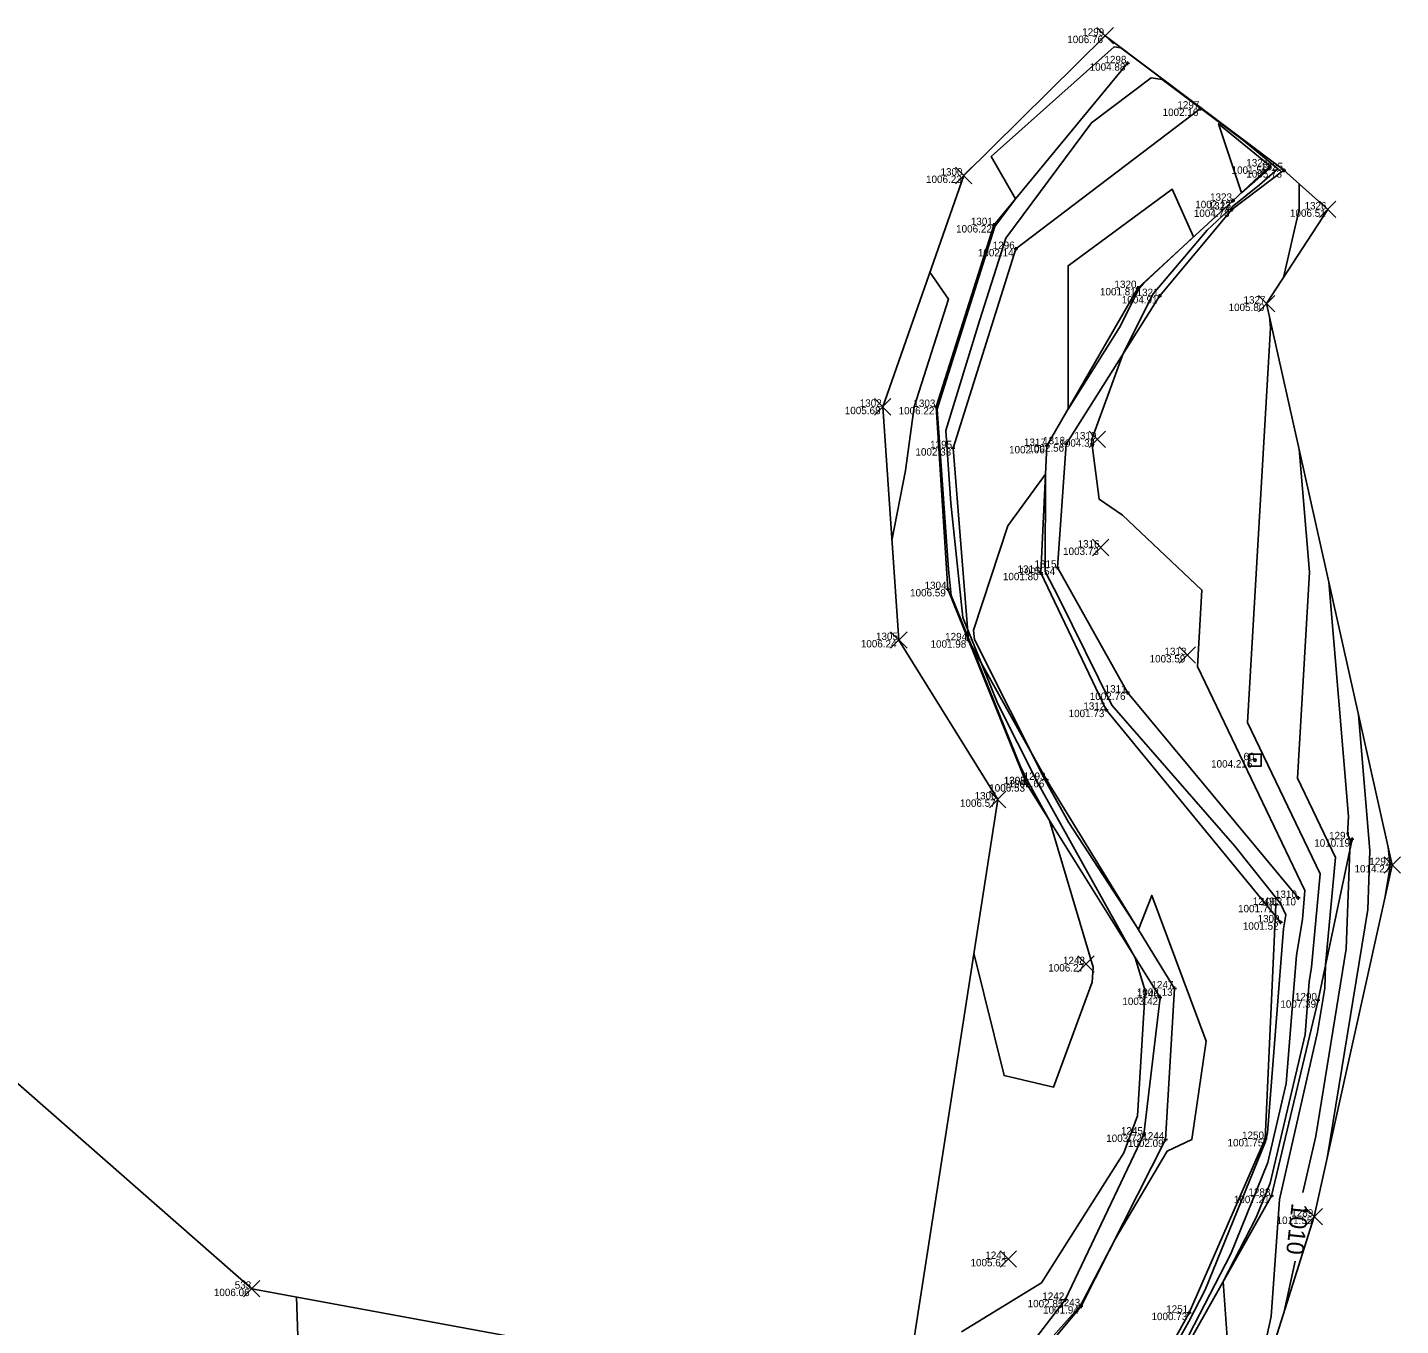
# Model space of a CAD drawing. Extents: x 2354693 to 2355622, y 637071 to 710080.
# Drawn here: x 2355399.4 to 2355622.2, y 709573.6 to 709784.2 of the extents above; entities that cross this region are included whole.
import ezdxf

# ---------------------------------------------------------------- set-up
doc = ezdxf.new("R2010")
doc.units = 0
for name, color, linetype in [('Default', 7, 'Continuous'), ('DT_X_Contour_Major', 7, 'Continuous'), ('DT_X_Contour_Minor', 7, 'Continuous'), ('HY_X_Water_Edge', 7, 'Continuous'), ('SV_X_Control_Cells_Found', 7, 'Continuous'), ('SV_X_Random_Point', 7, 'Continuous'), ('SV_X_Shot_Marker', 7, 'Continuous'), ('SV_X_Text_Elevation', 7, 'Continuous'), ('SV_X_Text_Name', 7, 'Continuous'), ('SV_X_Toe_of_Slope', 7, 'Continuous'), ('SV_X_Top_of_Bank', 7, 'Continuous')]:
    doc.layers.add(name, color=color, linetype=linetype)

msp = doc.modelspace()

# ---------------------------------------------------------------- linework, layer by layer
at = {"layer": 'Default'}
for points in [[(2355589.64, 709532.44), (2355608.23, 709591.27), (2355620.9, 709648.31), (2355600.49, 709739.39), (2355610.41, 709754.67), (2355603.31, 709761.03), (2355574.3, 709782.85), (2355551.34, 709760.16), (2355538.2, 709722.65), (2355540.82, 709684.81), (2355556.87, 709658.95), (2355543.09, 709570.18)], [(2355589.64, 709532.44), (2355608.23, 709591.27), (2355620.9, 709648.31), (2355600.49, 709739.39), (2355610.41, 709754.67), (2355603.31, 709761.03), (2355574.3, 709782.85), (2355551.34, 709760.16), (2355538.2, 709722.65), (2355540.82, 709684.81), (2355556.87, 709658.95), (2355543.09, 709570.18)], [(2355527.94, 709562.59), (2355435.81, 709579.57), (2355393.46, 709616.64), (2355345.61, 709656.34), (2355300.99, 709689.27), (2355286.64, 709699.9), (2355266.95, 709650.86), (2355232.94, 709607.57), (2355192.85, 709575.71), (2355160.05, 709542.81)], [(2355527.94, 709562.59), (2355435.81, 709579.57), (2355393.46, 709616.64), (2355345.61, 709656.34), (2355300.99, 709689.27), (2355286.64, 709699.9), (2355266.95, 709650.86), (2355232.94, 709607.57), (2355192.85, 709575.71), (2355160.05, 709542.81)]]:
    msp.add_lwpolyline(points, dxfattribs=at)
at = {"layer": 'DT_X_Contour_Major'}
for points in [[(2355610.61, 709694.24), (2355613.77, 709656.2), (2355613.6, 709653.34), (2355614.13, 709652.24), (2355613.99, 709650.75), (2355613.43, 709634.7), (2355608.47, 709604.33), (2355606.37, 709595.16)], [(2355610.61, 709694.24), (2355613.77, 709656.2), (2355613.6, 709653.34), (2355614.13, 709652.24), (2355613.99, 709650.75), (2355613.43, 709634.7), (2355608.47, 709604.33), (2355606.37, 709595.16)], [(2355605.14, 709584.05), (2355603.36, 709575.86)], [(2355605.14, 709584.05), (2355603.36, 709575.86)]]:
    msp.add_lwpolyline(points, dxfattribs=at)
at = {"layer": 'DT_X_Contour_Minor'}
for points in [[(2355553, 709634.03), (2355557.89, 709614.16), (2355565.94, 709612.27), (2355572.21, 709629.3), (2355572.35, 709631.71), (2355565.27, 709655.55), (2355561.95, 709661.5), (2355560.63, 709664.14), (2355560.61, 709664.14), (2355549.33, 709692.03), (2355548.89, 709696.25), (2355547.05, 709722.24), (2355547.6, 709724.01), (2355556.42, 709751.92), (2355559.77, 709756.4), (2355555.82, 709763.23), (2355575.76, 709781.05), (2355576.84, 709780.91), (2355595.66, 709766.78)], [(2355553, 709634.03), (2355557.89, 709614.16), (2355565.94, 709612.27), (2355572.21, 709629.3), (2355572.35, 709631.71), (2355565.27, 709655.55), (2355561.95, 709661.5), (2355560.63, 709664.14), (2355560.61, 709664.14), (2355549.33, 709692.03), (2355548.89, 709696.25), (2355547.05, 709722.24), (2355547.6, 709724.01), (2355556.42, 709751.92), (2355559.77, 709756.4), (2355555.82, 709763.23), (2355575.76, 709781.05), (2355576.84, 709780.91), (2355595.66, 709766.78)], [(2355550.99, 709572.6), (2355563.99, 709580.52), (2355577.32, 709601.59), (2355579.55, 709607.64), (2355580.78, 709627.91), (2355579.19, 709633.25), (2355563.25, 709661.79), (2355556.89, 709674.47), (2355556.88, 709674.47), (2355551.22, 709688.48), (2355549.28, 709706.99), (2355548.45, 709718.8), (2355553.93, 709736.58), (2355558.18, 709750.02), (2355572.11, 709768.7), (2355581.75, 709776.01), (2355583.57, 709775.77), (2355596.76, 709765.86), (2355602.34, 709761.28), (2355599.33, 709758.64), (2355594.9, 709755.07), (2355590.83, 709751.31), (2355582.08, 709741), (2355577.24, 709731.27), (2355572.08, 709717.21), (2355573.34, 709707.66), (2355577.14, 709705.05), (2355590.01, 709692.92), (2355589.29, 709680.51), (2355606.72, 709644.18), (2355606.3, 709639.49), (2355605.34, 709633.67), (2355603.7, 709612.85), (2355600.7, 709600.07), (2355594.68, 709585.25), (2355587.86, 709572.01)], [(2355550.99, 709572.6), (2355563.99, 709580.52), (2355577.32, 709601.59), (2355579.55, 709607.64), (2355580.78, 709627.91), (2355579.19, 709633.25), (2355563.25, 709661.79), (2355556.89, 709674.47), (2355556.88, 709674.47), (2355551.22, 709688.48), (2355549.28, 709706.99), (2355548.45, 709718.8), (2355553.93, 709736.58), (2355558.18, 709750.02), (2355572.11, 709768.7), (2355581.75, 709776.01), (2355583.57, 709775.77), (2355596.76, 709765.86), (2355602.34, 709761.28), (2355599.33, 709758.64), (2355594.9, 709755.07), (2355590.83, 709751.31), (2355582.08, 709741), (2355577.24, 709731.27), (2355572.08, 709717.21), (2355573.34, 709707.66), (2355577.14, 709705.05), (2355590.01, 709692.92), (2355589.29, 709680.51), (2355606.72, 709644.18), (2355606.3, 709639.49), (2355605.34, 709633.67), (2355603.7, 709612.85), (2355600.7, 709600.07), (2355594.68, 709585.25), (2355587.86, 709572.01)], [(2355596.42, 709757.37), (2355592.7, 709768.57), (2355601.22, 709761.58), (2355596.42, 709757.37)], [(2355596.42, 709757.37), (2355592.7, 709768.57), (2355601.22, 709761.58), (2355596.42, 709757.37)], [(2355568.3, 709722.28), (2355568.28, 709745.54), (2355585.19, 709757.94), (2355588.66, 709750.24), (2355580.55, 709742.73), (2355579.8, 709741.84), (2355576.65, 709735.52), (2355568.3, 709722.28)], [(2355568.3, 709722.28), (2355568.28, 709745.54), (2355585.19, 709757.94), (2355588.66, 709750.24), (2355580.55, 709742.73), (2355579.8, 709741.84), (2355576.65, 709735.52), (2355568.3, 709722.28)], [(2355605.76, 709758.83), (2355605.79, 709754.67), (2355603.24, 709743.63)], [(2355605.76, 709758.83), (2355605.79, 709754.67), (2355603.24, 709743.63)], [(2355539.7, 709700.97), (2355541.89, 709712.32), (2355543.32, 709722.63), (2355548.87, 709740.1), (2355545.86, 709744.51)], [(2355539.7, 709700.97), (2355541.89, 709712.32), (2355543.32, 709722.63), (2355548.87, 709740.1), (2355545.86, 709744.51)], [(2355600.97, 709737.27), (2355601.12, 709735.48), (2355597.4, 709671.45), (2355609.19, 709646.86), (2355607.81, 709631.74), (2355607.42, 709629.35), (2355606.75, 709620.83), (2355601.07, 709596.69), (2355598.81, 709591.11), (2355593.45, 709580.72), (2355594.25, 709569.36), (2355593.09, 709546.68), (2355590.78, 709536.05)], [(2355600.97, 709737.27), (2355601.12, 709735.48), (2355597.4, 709671.45), (2355609.19, 709646.86), (2355607.81, 709631.74), (2355607.42, 709629.35), (2355606.75, 709620.83), (2355601.07, 709596.69), (2355598.81, 709591.11), (2355593.45, 709580.72), (2355594.25, 709569.36), (2355593.09, 709546.68), (2355590.78, 709536.05)], [(2355605.79, 709715.76), (2355607.44, 709695.84), (2355605.5, 709662.4), (2355611.66, 709649.55), (2355610.07, 709632.1), (2355609.94, 709628.32), (2355608.77, 709621.18), (2355602.57, 709594.04), (2355601.22, 709575.06), (2355597.07, 709555.96)], [(2355605.79, 709715.76), (2355607.44, 709695.84), (2355605.5, 709662.4), (2355611.66, 709649.55), (2355610.07, 709632.1), (2355609.94, 709628.32), (2355608.77, 709621.18), (2355602.57, 709594.04), (2355601.22, 709575.06), (2355597.07, 709555.96)], [(2355556.66, 709561.53), (2355570.22, 709576.8), (2355570.74, 709577.68), (2355575.9, 709587.59), (2355584.36, 709601.9), (2355588.38, 709603.79), (2355590.7, 709619.75), (2355581.86, 709643.38), (2355579.69, 709637.83), (2355568.36, 709655.25), (2355564.55, 709662.08), (2355553.16, 709684.8), (2355553.16, 709684.8), (2355553.11, 709684.92), (2355552.96, 709686.4), (2355558.49, 709703.33), (2355564.64, 709711.73), (2355564.59, 709695.94), (2355566.8, 709691.65), (2355575.39, 709674.22), (2355595.34, 709651.37), (2355602.74, 709642.08), (2355603.62, 709640.2), (2355603.26, 709637.98), (2355600.65, 709604.87), (2355600.32, 709603.44), (2355590.55, 709579.39), (2355587.9, 709574.25), (2355577.82, 709556.22)], [(2355556.66, 709561.53), (2355570.22, 709576.8), (2355570.74, 709577.68), (2355575.9, 709587.59), (2355584.36, 709601.9), (2355588.38, 709603.79), (2355590.7, 709619.75), (2355581.86, 709643.38), (2355579.69, 709637.83), (2355568.36, 709655.25), (2355564.55, 709662.08), (2355553.16, 709684.8), (2355553.16, 709684.8), (2355553.11, 709684.92), (2355552.96, 709686.4), (2355558.49, 709703.33), (2355564.64, 709711.73), (2355564.59, 709695.94), (2355566.8, 709691.65), (2355575.39, 709674.22), (2355595.34, 709651.37), (2355602.74, 709642.08), (2355603.62, 709640.2), (2355603.26, 709637.98), (2355600.65, 709604.87), (2355600.32, 709603.44), (2355590.55, 709579.39), (2355587.9, 709574.25), (2355577.82, 709556.22)], [(2355615.43, 709672.73), (2355617.26, 709650.63), (2355616.93, 709641.07), (2355610.33, 709600.73)], [(2355615.43, 709672.73), (2355617.26, 709650.63), (2355616.93, 709641.07), (2355610.33, 709600.73)], [(2355620.25, 709651.22), (2355620.47, 709648.58), (2355620.43, 709647.44), (2355619.64, 709642.63)], [(2355620.25, 709651.22), (2355620.47, 709648.58), (2355620.43, 709647.44), (2355619.64, 709642.63)], [(2355443.41, 709568.67), (2355443.07, 709578.23)], [(2355443.41, 709568.67), (2355443.07, 709578.23)]]:
    msp.add_lwpolyline(points, dxfattribs=at)
at = {"layer": 'HY_X_Water_Edge'}
for points in [[(2355444.84, 709409.8), (2355493.39, 709446.46), (2355518.03, 709448.34), (2355539.67, 709472.16), (2355542.83, 709490.32), (2355537.69, 709525.78), (2355546.35, 709545.98), (2355551.46, 709553.96), (2355570.39, 709576.73), (2355584.11, 709603.77), (2355585.55, 709628.29), (2355564.78, 709662.12), (2355552.11, 709684.77), (2355549.62, 709715.93), (2355559.81, 709748.25), (2355589.77, 709771.03)], [(2355601.98, 709641.84), (2355600.27, 709603.87), (2355587.93, 709575.67), (2355574.93, 709552.02), (2355564.16, 709527.42), (2355560.86, 709513.6), (2355569.23, 709466.41), (2355552.57, 709436.48), (2355543.58, 709440.01), (2355530.89, 709431.5), (2355507.81, 709418.76), (2355493.48, 709407.24), (2355475.84, 709401.85), (2355468.12, 709405.11), (2355452.68, 709393.73)]]:
    msp.add_lwpolyline(points, dxfattribs=at)
at = {"layer": 'SV_X_Control_Cells_Found'}
msp.add_lwpolyline([(2355597.61, 709666.31), (2355599.59, 709666.31), (2355599.59, 709664.33), (2355597.61, 709664.33), (2355597.61, 709666.31)], dxfattribs=at)
msp.add_circle((2355598.6, 709665.32), 0.2, dxfattribs=at)
at = {"layer": 'SV_X_Random_Point'}
for p, q in [((2355572.97, 709781.52), (2355575.64, 709784.19)), ((2355572.97, 709784.19), (2355575.64, 709781.52)), ((2355550.01, 709758.83), (2355552.68, 709761.5)), ((2355550.01, 709761.5), (2355552.68, 709758.83)), ((2355609.07, 709753.34), (2355611.74, 709756.01)), ((2355609.07, 709756.01), (2355611.74, 709753.34)), ((2355599.16, 709738.06), (2355601.82, 709740.73)), ((2355599.16, 709740.73), (2355601.82, 709738.06)), ((2355536.86, 709721.31), (2355539.53, 709723.98)), ((2355536.86, 709723.98), (2355539.53, 709721.31)), ((2355571.71, 709716.03), (2355574.38, 709718.7)), ((2355571.71, 709718.7), (2355574.38, 709716.03)), ((2355572.25, 709698.48), (2355574.92, 709701.15)), ((2355572.25, 709701.15), (2355574.92, 709698.48)), ((2355539.48, 709683.47), (2355542.15, 709686.14)), ((2355539.48, 709686.14), (2355542.15, 709683.47)), ((2355586.3, 709681.03), (2355588.97, 709683.7)), ((2355586.3, 709683.7), (2355588.97, 709681.03)), ((2355555.54, 709657.61), (2355558.2, 709660.28)), ((2355555.54, 709660.28), (2355558.2, 709657.61)), ((2355619.57, 709646.97), (2355622.23, 709649.64)), ((2355619.57, 709649.64), (2355622.23, 709646.97)), ((2355569.88, 709630.9), (2355572.54, 709633.57)), ((2355569.88, 709633.57), (2355572.54, 709630.9)), ((2355606.9, 709589.94), (2355609.57, 709592.61)), ((2355606.9, 709592.61), (2355609.57, 709589.94)), ((2355557.24, 709583.06), (2355559.91, 709585.73)), ((2355557.24, 709585.73), (2355559.91, 709583.06)), ((2355434.48, 709578.23), (2355437.14, 709580.9)), ((2355434.48, 709580.9), (2355437.14, 709578.23))]:
    msp.add_line(p, q, dxfattribs=at)
at = {"layer": 'SV_X_Shot_Marker'}
for p, q in [((2355578.23, 709778.38), (2355577.63, 709778.38)), ((2355577.93, 709778.68), (2355577.93, 709778.08)), ((2355590.07, 709771.03), (2355589.47, 709771.03)), ((2355589.77, 709771.33), (2355589.77, 709770.73)), ((2355600.97, 709761.94), (2355600.97, 709761.34)), ((2355601.27, 709761.64), (2355600.67, 709761.64)), ((2355603.61, 709761.03), (2355603.01, 709761.03)), ((2355603.31, 709761.33), (2355603.31, 709760.73)), ((2355595.33, 709756.07), (2355594.73, 709756.07)), ((2355595.03, 709756.37), (2355595.03, 709755.77)), ((2355595.14, 709754.65), (2355594.54, 709754.65)), ((2355594.84, 709754.95), (2355594.84, 709754.35)), ((2355556.53, 709752.12), (2355555.93, 709752.12)), ((2355556.23, 709752.42), (2355556.23, 709751.82)), ((2355560.11, 709748.25), (2355559.51, 709748.25)), ((2355559.81, 709748.55), (2355559.81, 709747.95)), ((2355579.88, 709741.92), (2355579.28, 709741.92)), ((2355579.58, 709742.22), (2355579.58, 709741.62)), ((2355583.43, 709740.61), (2355582.83, 709740.61)), ((2355583.13, 709740.91), (2355583.13, 709740.31)), ((2355547.2, 709722.62), (2355546.6, 709722.62)), ((2355546.9, 709722.92), (2355546.9, 709722.32)), ((2355549.92, 709715.93), (2355549.32, 709715.93)), ((2355549.62, 709716.23), (2355549.62, 709715.63)), ((2355565.16, 709716.3), (2355564.56, 709716.3)), ((2355564.86, 709716.6), (2355564.86, 709716)), ((2355568.29, 709716.57), (2355567.69, 709716.57)), ((2355567.99, 709716.87), (2355567.99, 709716.27)), ((2355564.16, 709695.71), (2355563.56, 709695.71)), ((2355563.86, 709696.01), (2355563.86, 709695.41)), ((2355566.85, 709696.55), (2355566.25, 709696.55)), ((2355566.55, 709696.85), (2355566.55, 709696.25)), ((2355549.07, 709693.08), (2355548.47, 709693.08)), ((2355548.77, 709693.38), (2355548.77, 709692.78)), ((2355552.41, 709684.77), (2355551.81, 709684.77)), ((2355552.11, 709685.07), (2355552.11, 709684.47)), ((2355578.25, 709676.29), (2355577.65, 709676.29)), ((2355577.95, 709676.59), (2355577.95, 709675.99)), ((2355574.78, 709673.5), (2355574.18, 709673.5)), ((2355574.48, 709673.8), (2355574.48, 709673.2)), ((2355561.59, 709661.72), (2355561.59, 709661.12)), ((2355561.61, 709661.72), (2355561.61, 709661.12)), ((2355565.08, 709662.12), (2355564.48, 709662.12)), ((2355564.78, 709662.42), (2355564.78, 709661.82)), ((2355561.89, 709661.42), (2355561.29, 709661.42)), ((2355561.91, 709661.42), (2355561.31, 709661.42)), ((2355614.36, 709652.79), (2355614.36, 709652.19)), ((2355614.66, 709652.49), (2355614.06, 709652.49)), ((2355602.28, 709641.84), (2355601.68, 709641.84)), ((2355601.98, 709642.14), (2355601.98, 709641.54)), ((2355605.92, 709642.97), (2355605.32, 709642.97)), ((2355605.62, 709643.27), (2355605.62, 709642.67)), ((2355603.06, 709639.01), (2355602.46, 709639.01)), ((2355602.76, 709639.31), (2355602.76, 709638.71)), ((2355585.85, 709628.29), (2355585.25, 709628.29)), ((2355585.55, 709628.59), (2355585.55, 709627.99)), ((2355583.51, 709626.8), (2355582.91, 709626.8)), ((2355583.21, 709627.1), (2355583.21, 709626.5)), ((2355609.16, 709626.36), (2355608.56, 709626.36)), ((2355608.86, 709626.66), (2355608.86, 709626.06)), ((2355580.88, 709604.58), (2355580.28, 709604.58)), ((2355580.58, 709604.88), (2355580.58, 709604.28)), ((2355584.41, 709603.77), (2355583.81, 709603.77)), ((2355584.11, 709604.07), (2355584.11, 709603.47)), ((2355600.57, 709603.87), (2355599.97, 709603.87)), ((2355600.27, 709604.17), (2355600.27, 709603.57)), ((2355601.3, 709594.95), (2355601.3, 709594.35)), ((2355601.6, 709594.65), (2355601, 709594.65)), ((2355568.13, 709577.76), (2355567.53, 709577.76)), ((2355567.83, 709578.06), (2355567.83, 709577.46)), ((2355570.39, 709577.03), (2355570.39, 709576.43)), ((2355570.69, 709576.73), (2355570.09, 709576.73)), ((2355588.23, 709575.67), (2355587.63, 709575.67)), ((2355587.93, 709575.97), (2355587.93, 709575.37))]:
    msp.add_line(p, q, dxfattribs=at)
at = {"layer": 'SV_X_Toe_of_Slope'}
for points in [[(2355444.84, 709409.8), (2355493.39, 709446.46), (2355518.03, 709448.34), (2355539.67, 709472.16), (2355542.83, 709490.32), (2355537.69, 709525.78), (2355546.35, 709545.98), (2355551.46, 709553.96), (2355570.39, 709576.73), (2355584.11, 709603.77), (2355585.55, 709628.29), (2355564.78, 709662.12), (2355552.11, 709684.77), (2355549.62, 709715.93), (2355559.81, 709748.25), (2355589.77, 709771.03)], [(2355602.76, 709639.01), (2355574.48, 709673.5), (2355563.86, 709695.71), (2355564.86, 709716.3), (2355579.58, 709741.92), (2355595.03, 709756.07), (2355600.97, 709761.64)], [(2355601.98, 709641.84), (2355600.27, 709603.87), (2355587.93, 709575.67), (2355574.93, 709552.02), (2355564.16, 709527.42), (2355560.86, 709513.6), (2355569.23, 709466.41), (2355552.57, 709436.48), (2355543.58, 709440.01), (2355530.89, 709431.5), (2355507.81, 709418.76), (2355493.48, 709407.24), (2355475.84, 709401.85), (2355468.12, 709405.11), (2355452.68, 709393.73)]]:
    msp.add_lwpolyline(points, dxfattribs=at)
at = {"layer": 'SV_X_Top_of_Bank'}
for points in [[(2355577.93, 709778.38), (2355556.23, 709752.12), (2355546.9, 709722.62), (2355548.77, 709693.08), (2355561.59, 709661.42)], [(2355605.62, 709642.97), (2355577.95, 709676.29), (2355566.55, 709696.55), (2355567.99, 709716.57), (2355583.13, 709740.61), (2355594.84, 709754.65), (2355603.31, 709761.03)], [(2355543.09, 709570.18), (2355548.89, 709553.12), (2355567.83, 709577.76), (2355580.58, 709604.58), (2355583.21, 709626.8), (2355561.61, 709661.42)], [(2355539.65, 709419.5), (2355536.88, 709428.91), (2355545.13, 709427.91), (2355562.31, 709433.11), (2355572.18, 709444.95), (2355572.3, 709459.52), (2355577.24, 709476.89), (2355570.97, 709503.21), (2355563.87, 709514.15), (2355574.03, 709537.88), (2355587.83, 709570.74), (2355601.3, 709594.65), (2355608.86, 709626.36), (2355614.36, 709652.49)]]:
    msp.add_lwpolyline(points, dxfattribs=at)

# ---------------------------------------------------------------- texts
at = {"layer": 'DT_X_Contour_Major'}
msp.add_text('1010', height=2.8, rotation=263.666, dxfattribs=at).set_placement((2355604.58, 709593.54))
msp.add_text('1010', height=2.8, rotation=263.666, dxfattribs=at).set_placement((2355604.58, 709593.54))
at = {"layer": 'SV_X_Text_Elevation'}
for s, p in [('1006.76', (2355568.15, 709781.65)), ('1004.88', (2355571.78, 709777.18)), ('1002.16', (2355583.62, 709769.83)), ('1006.23', (2355545.23, 709758.96)), ('1001.56', (2355594.82, 709760.44)), ('1005.73', (2355597.2, 709759.83)), ('1002.13', (2355588.92, 709754.87)), ('1004.78', (2355588.69, 709753.45)), ('1006.51', (2355604.29, 709753.47)), ('1006.22', (2355550.11, 709750.92)), ('1002.14', (2355553.64, 709747.05)), ('1001.81', (2355573.46, 709740.72)), ('1004.91', (2355577, 709739.41)), ('1005.80', (2355594.33, 709738.19)), ('1005.68', (2355532.05, 709721.45)), ('1006.22', (2355540.78, 709721.42)), ('1004.34', (2355566.87, 709716.17)), ('1002.33', (2355543.51, 709714.73)), ('1002.06', (2355558.71, 709715.1)), ('1002.56', (2355561.84, 709715.37)), ('1003.73', (2355567.47, 709698.61)), ('1001.80', (2355557.7, 709694.51)), ('1002.54', (2355560.38, 709695.35)), ('1006.59', (2355542.64, 709691.88)), ('1006.24', (2355534.65, 709683.61)), ('1001.98', (2355545.96, 709683.57)), ('1003.59', (2355581.51, 709681.17)), ('1002.76', (2355571.8, 709675.09)), ('1001.73', (2355568.37, 709672.3)), ('1004.216', (2355591.49, 709664.12)), ('1001.66', (2355558.63, 709660.92)), ('1006.53', (2355555.48, 709660.22)), ('1006.53', (2355555.5, 709660.22)), ('1006.57', (2355550.73, 709657.75)), ('1010.19', (2355608.23, 709651.29)), ('1014.27', (2355614.76, 709647.11)), ('1001.71', (2355595.86, 709640.64)), ('1003.10', (2355599.46, 709641.77)), ('1001.52', (2355596.64, 709637.81)), ('1006.27', (2355565.07, 709631.03)), ('1002.13', (2355579.44, 709627.09)), ('1003.42', (2355577.09, 709625.6)), ('1007.39', (2355602.73, 709625.16)), ('1003.72', (2355574.47, 709603.38)), ('1002.09', (2355577.98, 709602.57)), ('1001.75', (2355594.16, 709602.67)), ('1007.21', (2355595.18, 709593.45)), ('1011.55', (2355602.12, 709590.07)), ('1005.62', (2355552.45, 709583.2)), ('1006.06', (2355429.66, 709578.37)), ('1002.85', (2355561.72, 709576.56)), ('1001.94', (2355564.22, 709575.53)), ('1000.73', (2355581.82, 709574.47))]:
    msp.add_text(s, height=1.2, dxfattribs=at).set_placement(p)
at = {"layer": 'SV_X_Text_Name'}
for s, p in [('1299', (2355570.57, 709782.85)), ('1298', (2355574.18, 709778.38)), ('1297', (2355586.02, 709771.03)), ('1324', (2355597.2, 709761.64)), ('1325', (2355599.59, 709761.03)), ('1300', (2355547.58, 709760.16)), ('1322', (2355591.11, 709754.65)), ('1323', (2355591.32, 709756.07)), ('1326', (2355606.65, 709754.67)), ('1301', (2355552.5, 709752.12)), ('1296', (2355556.05, 709748.25)), ('1320', (2355575.81, 709741.92)), ('1321', (2355579.4, 709740.61)), ('1327', (2355596.75, 709739.39)), ('1302', (2355534.47, 709722.65)), ('1303', (2355543.18, 709722.62)), ('1317', (2355561.12, 709716.3)), ('1318', (2355564.23, 709716.57)), ('1319', (2355569.31, 709717.37)), ('1295', (2355545.89, 709715.93)), ('1316', (2355569.83, 709699.81)), ('1315', (2355562.83, 709696.55)), ('1314', (2355560.08, 709695.71)), ('1304', (2355544.99, 709693.08)), ('1305', (2355537.1, 709684.81)), ('1294', (2355548.33, 709684.77)), ('1313', (2355583.92, 709682.37)), ('1311', (2355574.22, 709676.29)), ('1312', (2355570.76, 709673.5)), ('60', (2355596.75, 709665.32)), ('1308', (2355557.83, 709661.42)), ('1307', (2355557.86, 709661.42)), ('1293', (2355561.06, 709662.12)), ('1306', (2355553.11, 709658.95)), ('1291', (2355610.63, 709652.49)), ('1292', (2355617.17, 709648.31)), ('1310', (2355601.85, 709642.97)), ('1249', (2355598.25, 709641.84)), ('1309', (2355599.03, 709639.01)), ('1248', (2355567.46, 709632.23)), ('1247', (2355581.81, 709628.29)), ('1246', (2355579.46, 709626.8)), ('1290', (2355605.1, 709626.36)), ('1245', (2355576.86, 709604.58)), ('1244', (2355580.33, 709603.77)), ('1250', (2355596.51, 709603.87)), ('1288', (2355597.55, 709594.65)), ('1289', (2355604.5, 709591.27)), ('1241', (2355554.84, 709584.4)), ('533', (2355433.05, 709579.57)), ('1242', (2355564.1, 709577.76)), ('1243', (2355566.68, 709576.73)), ('1251', (2355584.2, 709575.67))]:
    msp.add_text(s, height=1.2, dxfattribs=at).set_placement(p)

doc.saveas('drawing.dxf')
